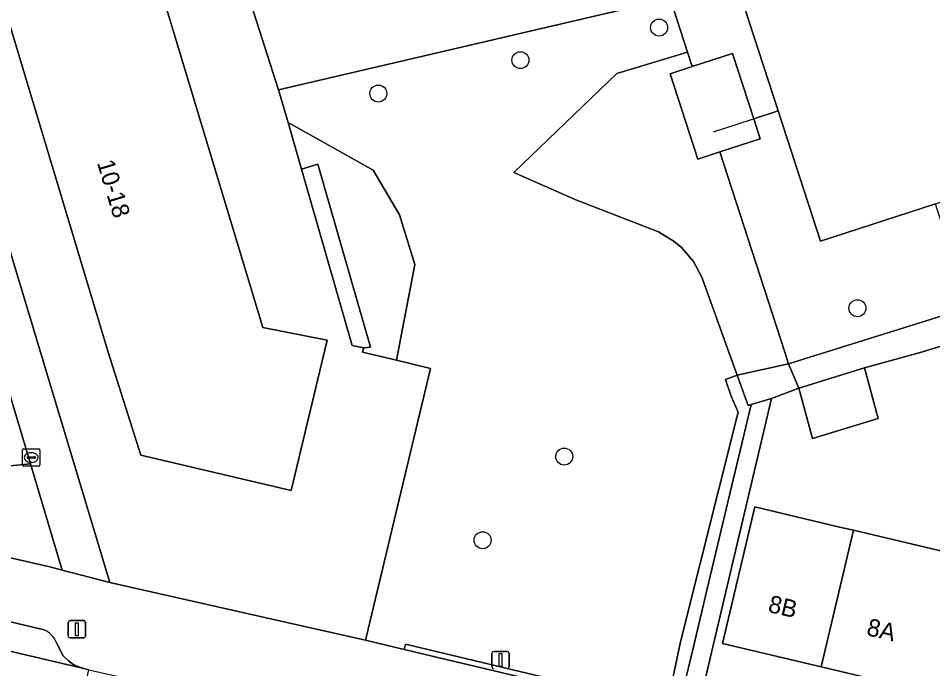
# Model space of a CAD drawing. Extents: x 159716 to 160783, y 383290 to 384031.
# Drawn here: x 160111.9 to 160164.5, y 383481.8 to 383519.2 of the extents above; entities that cross this region are included whole.
import ezdxf

# ---------------------------------------------------------------- set-up
doc = ezdxf.new("R2010")
doc.units = 0
for name, color, linetype in [('IMGEO_Boom', 7, 'Continuous'), ('IMGEO_Erf', 7, 'Continuous'), ('IMGEO_Grasland_overig', 7, 'Continuous'), ('IMGEO_Groenvoorziening', 7, 'Continuous'), ('IMGEO_Haag', 7, 'Continuous'), ('IMGEO_Hek', 7, 'Continuous'), ('IMGEO_Kolk', 7, 'Continuous'), ('IMGEO_Lichtmast', 7, 'Continuous'), ('IMGEO_Pand', 7, 'Continuous'), ('IMGEO_Pand_nummerreeks', 7, 'Continuous'), ('IMGEO_Parkeervlak_open', 7, 'Continuous'), ('IMGEO_Rijbaan_lokaal_open', 7, 'Continuous'), ('IMGEO_Verkeersbordpaal', 7, 'Continuous'), ('IMGEO_Voetpad_open', 7, 'Continuous')]:
    doc.layers.add(name, color=color, linetype=linetype)

msp = doc.modelspace()

# ---------------------------------------------------------------- linework, layer by layer
at = {"layer": 'IMGEO_Boom'}
for centre in [(160148.732, 383518.68), (160140.749, 383516.806), (160132.571, 383514.886), (160160.139, 383502.528), (160143.271, 383493.989), (160138.574, 383489.174)]:
    msp.add_circle(centre, 0.489, dxfattribs=at)
at = {"layer": 'IMGEO_Erf'}
for points in [[(160109.974, 383510.449), (160113.121, 383500), (160117.113, 383486.747), (160127.298, 383484.43), (160131.838, 383483.422), (160131.873, 383483.568), (160135.573, 383499.062), (160133.621, 383499.531), (160131.668, 383500), (160131.743, 383500.251), (160131.075, 383500.388), (160128.145, 383510.541), (160127.373, 383513.217), (160126.833, 383515.089), (160119.867, 383536.852)], [(160085.14, 383516.351), (160119.521, 383526.767), (160120.143, 383524.713), (160120.182, 383524.584), (160119.047, 383524.242), (160125.923, 383501.413), (160129.624, 383500.686), (160127.557, 383492.028), (160118.898, 383494.078), (160117.025, 383500), (160110.499, 383521.668)], [(160171.086, 383502.238), (160163.828, 383500), (160160.54, 383499.088), (160161.343, 383496.175), (160157.562, 383495.032), (160156.763, 383497.927), (160155.188, 383497.336), (160150.838, 383478.892), (160150.634, 383478.026), (160168.912, 383473.579)]]:
    msp.add_lwpolyline(points, dxfattribs=at)
msp.add_lwpolyline([(160167.302, 383490.813), (160172.229, 383491.024), (160171.209, 383494.223), (160173.649, 383494.999), (160175.11, 383490.416), (160180.441, 383492.113), (160181.08, 383492.316), (160185.824, 383493.861), (160188.301, 383486.132), (160182.889, 383484.412), (160177.562, 383482.719), (160171.781, 383480.881), (160171.612, 383481.415), (160167.736, 383481.241), (160163.833, 383481.066), (160163.708, 383480.541), (160158.052, 383481.884), (160152.381, 383483.23), (160154.242, 383491.087), (160159.112, 383489.934), (160159.915, 383489.744), (160165.575, 383488.403), (160165.24, 383486.988), (160167.462, 383487.082)], close=True, dxfattribs=at)
at = {"layer": 'IMGEO_Grasland_overig'}
msp.add_lwpolyline([(160171.086, 383502.238), (160171.073, 383502.28), (160174.925, 383503.521), (160174.954, 383503.431), (160176.547, 383503.922), (160176.046, 383505.497), (160166.551, 383502.574), (160158.329, 383500), (160156.175, 383499.326), (160156.763, 383497.927), (160160.54, 383499.088), (160163.828, 383500)], close=True, dxfattribs=at)
at = {"layer": 'IMGEO_Groenvoorziening'}
for points in [[(160143.606, 383547.246), (160128.377, 383542.719), (160127.289, 383543.247), (160121.907, 383538.609), (160119.867, 383536.852), (160126.833, 383515.089), (160149.362, 383520.377), (160146.927, 383527.973), (160148.885, 383528.612), (160148.664, 383529.265), (160146.193, 383530.442), (160144.646, 383528.631), (160143.977, 383529.196), (160145.964, 383531.544), (160148.288, 383530.46), (160148.907, 383530.645)], [(160151.395, 383526.752), (160149.671, 383526.297), (160149.114, 383527.938), (160147.905, 383527.545), (160148.762, 383524.808), (160150.111, 383520.62), (160149.362, 383520.377), (160150.368, 383517.267), (160150.637, 383516.435), (160152.962, 383517.188), (160154.18, 383513.433), (160155.574, 383513.885)], [(160152.227, 383511.524), (160150.966, 383511.115), (160149.374, 383516.025), (160150.637, 383516.435), (160150.368, 383517.267), (160146.296, 383516.036), (160140.373, 383510.346), (160143.93, 383508.758), (160148.699, 383506.92), (160149.605, 383506.366), (160150.009, 383506.021), (160150.699, 383505.214), (160151.193, 383504.314), (160152.75, 383500), (160153.228, 383498.674), (160156.175, 383499.326), (160155.957, 383500)], [(160133.783, 383507.895), (160132.278, 383510.476), (160127.373, 383513.217), (160128.145, 383510.541), (160129.096, 383510.813), (160132.13, 383500.29), (160131.743, 383500.251), (160131.668, 383500), (160133.621, 383499.531), (160134.669, 383505.041)], [(160128.145, 383510.541), (160131.075, 383500.388), (160131.743, 383500.251), (160132.13, 383500.29), (160129.096, 383510.813)], [(160134.131, 383483.184), (160134.066, 383482.891), (160147.229, 383479.752), (160149.116, 383479.302), (160149.777, 383479.145), (160150.701, 383483.027), (160151.576, 383486.699), (160152.588, 383490.952), (160154.023, 383496.977), (160153.858, 383496.926), (160153.228, 383498.674), (160152.559, 383498.433), (160152.883, 383497.456), (160153.275, 383496.549), (160149.96, 383483.331), (160149.178, 383479.598), (160147.3, 383480.044)]]:
    msp.add_lwpolyline(points, close=True, dxfattribs=at)
for points in [[(160149.178, 383479.598), (160149.96, 383483.331), (160153.275, 383496.549), (160152.883, 383497.456), (160152.559, 383498.433), (160153.228, 383498.674), (160152.75, 383500), (160151.193, 383504.314), (160150.699, 383505.214), (160150.009, 383506.021), (160149.605, 383506.366), (160148.699, 383506.92), (160143.93, 383508.758), (160140.373, 383510.346), (160146.296, 383516.036), (160150.368, 383517.267), (160149.362, 383520.377), (160126.833, 383515.089), (160127.373, 383513.217), (160132.278, 383510.476), (160133.783, 383507.895), (160134.669, 383505.041), (160133.621, 383499.531), (160135.573, 383499.062), (160131.873, 383483.568), (160131.838, 383483.422), (160134.066, 383482.891), (160134.131, 383483.184), (160147.3, 383480.044)], [(160111.391, 383493.449), (160112.552, 383493.574), (160109.64, 383503.302), (160108.104, 383502.829)], [(160101.544, 383490.395), (160113.66, 383487.636), (160114.386, 383487.449), (160112.552, 383493.574), (160111.391, 383493.449)]]:
    msp.add_lwpolyline(points, dxfattribs=at)
at = {"layer": 'IMGEO_Haag'}
msp.add_lwpolyline([(160134.131, 383483.184), (160134.066, 383482.891), (160147.229, 383479.752), (160149.116, 383479.302), (160149.777, 383479.145), (160150.701, 383483.027), (160151.576, 383486.699), (160152.588, 383490.952), (160154.023, 383496.977), (160153.858, 383496.926), (160153.228, 383498.674), (160152.559, 383498.433), (160152.883, 383497.456), (160153.275, 383496.549), (160149.96, 383483.331), (160149.178, 383479.598), (160147.3, 383480.044)], close=True, dxfattribs=at)
at = {"layer": 'IMGEO_Hek'}
msp.add_lwpolyline([(160151.853, 383512.679), (160155.514, 383513.866)], dxfattribs=at)
at = {"layer": 'IMGEO_Kolk'}
for p, q in [((160112.097, 383493.506), (160112.097, 383494.358)), ((160112.172, 383494.432), (160113.024, 383494.432)), ((160112.585, 383494.212), (160112.61, 383494.212)), ((160113.098, 383494.358), (160113.098, 383493.506)), ((160112.356, 383493.926), (160112.356, 383493.938)), ((160112.794, 383493.889), (160112.396, 383493.889)), ((160112.399, 383493.975), (160112.797, 383493.975)), ((160112.608, 383493.652), (160112.583, 383493.652)), ((160112.84, 383493.938), (160112.84, 383493.926)), ((160113.024, 383493.432), (160112.172, 383493.432))]:
    msp.add_line(p, q, dxfattribs=at)
for points in [[(160112.097, 383493.506), (160112.097, 383494.358)], [(160112.172, 383494.432), (160113.024, 383494.432)], [(160113.098, 383494.358), (160113.098, 383493.506)], [(160113.024, 383493.432), (160112.172, 383493.432)]]:
    msp.add_lwpolyline(points, dxfattribs=at)
for centre, radius, start, end in [((160112.174, 383494.356), 0.0765, 91.552, 178.448), ((160112.174, 383494.356), 0.0765, 91.552, 178.448), ((160113.022, 383494.356), 0.0765, 1.552, 88.448), ((160113.022, 383494.356), 0.0765, 1.552, 88.448), ((160112.396, 383493.935), 0.0403, 85.8775, 175.7526), ((160112.393, 383493.925), 0.0366, 178.938, 274.7102), ((160112.797, 383493.932), 0.043, 264.8664, 352.4533), ((160112.801, 383493.937), 0.0386, 1.7309, 96.639), ((160112.174, 383493.508), 0.0765, 181.552, 268.448), ((160112.174, 383493.508), 0.0765, 181.552, 268.448), ((160113.022, 383493.508), 0.0765, 271.552, 358.448), ((160113.022, 383493.508), 0.0765, 271.552, 358.448)]:
    msp.add_arc(centre, radius, start, end, dxfattribs=at)
for centre, major_axis, ratio, start_param, end_param in [((160112.584, 383493.932), (-0.387, 0.002), 0.722429, 4.712389, 7.853982), ((160112.609, 383493.932), (-0.39, 0.002), 0.717154, 1.570796, 4.712389)]:
    msp.add_ellipse(centre, major_axis=major_axis, ratio=ratio, start_param=start_param, end_param=end_param, dxfattribs=at)
at = {"layer": 'IMGEO_Lichtmast'}
for p, q in [((160114.728, 383483.651), (160114.728, 383484.451)), ((160114.728, 383484.451), (160114.728, 383483.651)), ((160114.828, 383484.551), (160115.618, 383484.551)), ((160115.618, 383484.551), (160114.828, 383484.551)), ((160115.718, 383484.451), (160115.718, 383483.651)), ((160115.718, 383483.651), (160115.718, 383484.451)), ((160115.618, 383483.551), (160114.828, 383483.551)), ((160114.828, 383483.551), (160115.618, 383483.551))]:
    msp.add_line(p, q, dxfattribs=at)
msp.add_lwpolyline([(160115.148, 383484.426), (160115.298, 383484.426), (160115.298, 383483.676), (160115.148, 383483.676), (160115.148, 383484.426)], dxfattribs=at)
for centre, start, end in [((160114.828, 383484.451), 90, 180), ((160114.828, 383484.451), 90, 180), ((160115.618, 383484.451), 0, 90), ((160115.618, 383484.451), 360, 90), ((160114.828, 383483.651), 180, 270), ((160114.828, 383483.651), 180, 270), ((160115.618, 383483.651), 270, 0), ((160115.618, 383483.651), 270, 0)]:
    msp.add_arc(centre, 0.1, start, end, dxfattribs=at)
at = {"layer": 'IMGEO_Pand'}
for points in [[(160174.562, 383521.735), (160173.289, 383525.659), (160171.518, 383531.116), (160170.889, 383533.055), (160151.395, 383526.752), (160155.574, 383513.885), (160158.009, 383506.387), (160164.625, 383508.535), (160177.491, 383512.712)], [(160119.047, 383524.242), (160115.287, 383523.11), (160110.499, 383521.668), (160117.025, 383500), (160118.898, 383494.078), (160127.557, 383492.028), (160129.624, 383500.686), (160125.923, 383501.413)], [(160154.18, 383513.433), (160152.962, 383517.188), (160150.637, 383516.435), (160149.374, 383516.025), (160150.966, 383511.115), (160152.227, 383511.524), (160154.554, 383512.279)], [(160156.763, 383497.927), (160157.562, 383495.032), (160161.343, 383496.175), (160160.54, 383499.088)], [(160159.915, 383489.744), (160159.112, 383489.934), (160154.242, 383491.087), (160152.381, 383483.23), (160158.052, 383481.884)], [(160167.523, 383487.085), (160167.462, 383487.082), (160165.24, 383486.988), (160165.575, 383488.403), (160159.915, 383489.744), (160158.052, 383481.884), (160163.708, 383480.541), (160163.833, 383481.066), (160167.736, 383481.241)]]:
    msp.add_lwpolyline(points, close=True, dxfattribs=at)
at = {"layer": 'IMGEO_Parkeervlak_open'}
for points in [[(160030.39, 383501.718), (160037.998, 383500), (160115.615, 383481.783), (160115.214, 383481.919), (160114.99, 383482.038), (160114.733, 383482.223), (160114.438, 383482.525), (160114.058, 383483.274)], [(160113.335, 383484.024), (160092.655, 383488.916), (160074.56, 383493.196)]]:
    msp.add_lwpolyline(points, dxfattribs=at)
msp.add_arc((160112.663, 383482.653), 1.527, 24.0073, 63.8924, dxfattribs=at)
at = {"layer": 'IMGEO_Rijbaan_lokaal_open'}
msp.add_lwpolyline([(160037.998, 383500), (160030.39, 383501.718), (160026.229, 383503.016), (160025.764, 383503.184), (160025.553, 383503.261), (160025.287, 383503.349), (160023.952, 383498.899), (160026.851, 383497.979), (160029.484, 383497.298), (160049.062, 383492.672), (160049.223, 383492.632), (160052.896, 383491.782), (160053.073, 383491.741), (160075.473, 383486.534), (160076.614, 383486.267), (160114.655, 383477.395), (160114.912, 383477.335), (160115.92, 383481.713), (160115.615, 383481.783)], close=True, dxfattribs=at)
at = {"layer": 'IMGEO_Verkeersbordpaal'}
for p, q in [((160139.11, 383481.876), (160139.11, 383482.676)), ((160139.11, 383482.676), (160139.11, 383481.876)), ((160139.21, 383482.776), (160140, 383482.776)), ((160140, 383482.776), (160139.21, 383482.776)), ((160140.1, 383482.676), (160140.1, 383481.876)), ((160140.1, 383481.876), (160140.1, 383482.676))]:
    msp.add_line(p, q, dxfattribs=at)
msp.add_lwpolyline([(160139.53, 383482.651), (160139.68, 383482.651), (160139.68, 383481.901), (160139.53, 383481.901), (160139.53, 383482.651)], dxfattribs=at)
for centre, start, end in [((160139.21, 383482.676), 90, 180), ((160139.21, 383482.676), 90, 180), ((160140, 383482.676), 0, 90), ((160140, 383482.676), 360, 90), ((160139.21, 383481.876), 180, 270), ((160139.21, 383481.876), 180, 270), ((160140, 383481.876), 270, 0), ((160140, 383481.876), 270, 0)]:
    msp.add_arc(centre, 0.1, start, end, dxfattribs=at)
at = {"layer": 'IMGEO_Voetpad_open'}
for points in [[(160165.248, 383506.607), (160164.625, 383508.535), (160158.009, 383506.387), (160155.574, 383513.885), (160154.18, 383513.433), (160154.554, 383512.279), (160152.227, 383511.524), (160155.957, 383500), (160156.175, 383499.326), (160158.329, 383500), (160166.551, 383502.574)], [(160109.974, 383510.449), (160096.86, 383506.543), (160096.728, 383505.71), (160098.239, 383503.88), (160099.742, 383504.34), (160105.557, 383506.121), (160108.524, 383507.029), (160109.64, 383503.302), (160112.552, 383493.574), (160114.386, 383487.449), (160117.113, 383486.747), (160113.121, 383500)], [(160156.175, 383499.326), (160153.228, 383498.674), (160153.858, 383496.926), (160154.023, 383496.977), (160155.188, 383497.336), (160156.763, 383497.927)], [(160155.188, 383497.336), (160154.023, 383496.977), (160152.588, 383490.952), (160151.576, 383486.699), (160150.701, 383483.027), (160149.777, 383479.145), (160150.838, 383478.892)]]:
    msp.add_lwpolyline(points, close=True, dxfattribs=at)
for points in [[(160033.63, 383502.95), (160051.319, 383498.726), (160051.408, 383499.106), (160055.09, 383498.247), (160054.996, 383497.847), (160070.904, 383494.048), (160071.018, 383494.535), (160074.674, 383493.682), (160074.56, 383493.196), (160092.655, 383488.916), (160113.335, 383484.024)], [(160194.475, 383480.623), (160194.15, 383481.64), (160192.457, 383481.099), (160168.912, 383473.579), (160150.634, 383478.026), (160150.838, 383478.892), (160149.777, 383479.145), (160149.116, 383479.302), (160147.229, 383479.752), (160134.066, 383482.891), (160131.838, 383483.422), (160127.298, 383484.43), (160117.113, 383486.747), (160114.386, 383487.449), (160113.66, 383487.636), (160101.544, 383490.395)], [(160114.058, 383483.274), (160114.438, 383482.525), (160114.733, 383482.223), (160114.99, 383482.038), (160115.214, 383481.919), (160115.615, 383481.783), (160115.92, 383481.713), (160118.629, 383481.089), (160134.274, 383477.578), (160137.094, 383476.945)]]:
    msp.add_lwpolyline(points, dxfattribs=at)
msp.add_arc((160112.663, 383482.653), 1.527, 24.0073, 63.8924, dxfattribs=at)

# ---------------------------------------------------------------- texts
at = {"layer": 'IMGEO_Pand_nummerreeks'}
for s, rotation, p in [('10-18', 286.7645, (160116.371, 383510.912)), ('8B', 346.7303, (160154.949, 383485.057)), ('8A', 346.7303, (160160.615, 383483.721))]:
    msp.add_text(s, height=1, rotation=rotation, dxfattribs=at).set_placement(p)

doc.saveas('drawing.dxf')
